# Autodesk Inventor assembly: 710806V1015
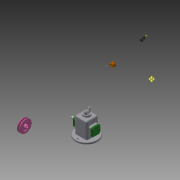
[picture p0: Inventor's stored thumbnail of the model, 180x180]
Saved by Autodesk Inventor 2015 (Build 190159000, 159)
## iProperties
Created: 2021-08
Part Number: 710806V1015
Document SubType Name: Assembly
Designer: 1054878
Author: 1054878
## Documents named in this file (16)
- C:\Users\1054878\Desktop\710806V1015 (1)\710806V1015.iam
- C:\Users\1054878\Desktop\710806V1015 (1)\V벨트풀리.ipt
- C:\Users\1054878\Desktop\710806V1015 (1)\고정핀 1.2x8.ipt
- C:\Users\1054878\Desktop\710806V1015 (1)\뒤커버.ipt
- C:\Users\1054878\Desktop\710806V1015 (1)\링크.ipt
- C:\Users\1054878\Desktop\710806V1015 (1)\멈춤나사 M3x8.ipt
- C:\Users\1054878\Desktop\710806V1015 (1)\베어링 12x32x10.ipt
- C:\Users\1054878\Desktop\710806V1015 (1)\본체.ipt
- C:\Users\1054878\Desktop\710806V1015 (1)\볼트 M4.ipt
- C:\Users\1054878\Desktop\710806V1015 (1)\부시.ipt
- C:\Users\1054878\Desktop\710806V1015 (1)\슬라이드.ipt
- C:\Users\1054878\Desktop\710806V1015 (1)\앞커버.ipt
- C:\Users\1054878\Desktop\710806V1015 (1)\오일 실 12 25 7.ipt
- C:\Users\1054878\Desktop\710806V1015 (1)\키 4x4x10.ipt
- C:\Users\1054878\Desktop\710806V1015 (1)\편심축.ipt
- C:\Users\1054878\Desktop\710806V1015 (1)\핀 5x18.ipt
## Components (3 placed, 3 different names)
1. V벨트풀리:1
2. 고정핀 1.2x8:1
3. 핀 5x18:1
